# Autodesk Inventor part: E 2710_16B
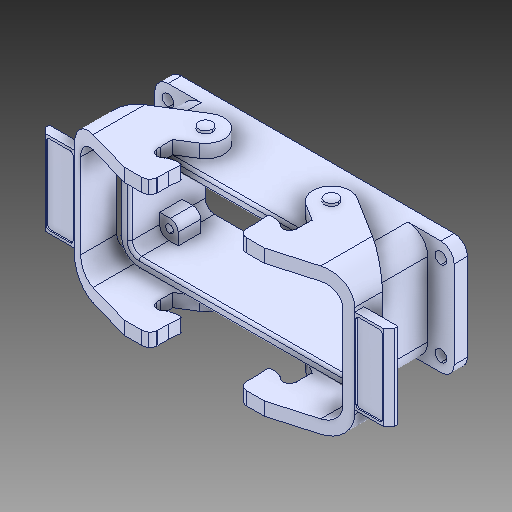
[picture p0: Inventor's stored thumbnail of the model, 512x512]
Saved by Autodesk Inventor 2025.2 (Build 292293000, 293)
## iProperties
Created: 2025-05
Part Number: E 2710_16B
Material: Všeobecné
Document SubType Name: Modeling
Designer: Patrik
Density: 1 g/cm^3
Appearance: Výchozí
Description: Kryt zástrčky se dvěma příčnými pákami
Stock Number: E 2710_16B
Author: Patrik
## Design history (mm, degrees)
feature "Base1"
node "Těleso1"
